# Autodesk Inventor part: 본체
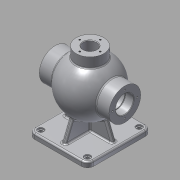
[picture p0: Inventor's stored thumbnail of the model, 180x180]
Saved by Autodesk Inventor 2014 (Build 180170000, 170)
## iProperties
Created: 2015-10
Part Number: 본체
Material: 알루미늄 6061
Document SubType Name: Modeling
Designer: youjin05
Density: 2.71 g/cm^3
Appearance: 알루미늄 - 평지
Mass: 1509.57 g
Surface Area: 1153.7 cm^2
Volume: 557.037 cm^3
Author: youjin05
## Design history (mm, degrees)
sketch "스케치1"
  geometry: L1 (-57.5, -62.5)-(57.5, -62.5); L2 (57.5, -62.5)-(57.5, 62.5); L3 (57.5, 62.5)-(-57.5, 62.5); L4 (-57.5, 62.5)-(-57.5, -62.5); L5 (-57.5, -62.5)-(57.5, 62.5); L6 (57.5, -62.5)-(-57.5, 62.5); 1 further point
  constraints: 12 end point, 2 midpoint, 2 parallel, 1 horizontal, 1 perpendicular
  dimensions: "d0" = 115 distance of L3.end L2.end; "d1" = 125 distance of L2.end L1.end
extrude "돌출1" new body sketch "스케치1" distance "d2" = 10; taper "d3" = 0 deg
sketch "스케치2"
  geometry: L1 (-57.5, 0)-(57.5, 0) reference; L2 (0, 32)-(0, 138); A1 r 53 centre (0, 85) between (0, 32) and (0, 138); 5 further points
  constraints: 3 midpoint, 3 point on circle, 3 vertical alignment, 2 end point, 1 centre point, 1 horizontal alignment, 1 perpendicular
  dimensions: "d6" = 53 radius of A1; "d7" = 85 distance of point (0, 0) A1.centre
revolve "회전1" sketch "스케치2" stored, may be unused: angle "d8" = 90 deg
node "작업 평면1"
sketch "스케치3"
  geometry: C1 r 53 at (0, 85) reference; C2 r 31 at (0, 85); 1 further point
  constraints: 1 centre point, 1 coincident
  dimensions: "d10" = 62 diameter of C2
extrude "돌출2" join sketch "스케치3" distance "d11" = 136; taper "d12" = 0 deg
node "작업 평면2"
sketch "스케치4"
  geometry: C1 r 27 at (0, 0); 1 further point
  constraints: 1 centre point, 1 coincident
  dimensions: "d14" = 54 diameter of C1
extrude "돌출3" join sketch "스케치4" stored distance "d15" = 136; taper "d16" = 0 deg
sketch "스케치5"
  geometry: L1 (-33.719, 44.109)-(-47.5, 10); L2 (-57.5, 0)-(57.5, 0) reference; L3 (57.5, 0)-(57.5, 10) reference; L4 (-57.5, 10)-(57.5, 10) reference; L5 (-57.5, 0)-(-57.5, 10) reference; L6 (-57.5, 10)-(57.5, 10) reference; L7 (-57.5, 0)-(-57.5, 10) reference; L8 (33.719, 44.109)-(47.5, 10); A1 r 53 centre (0, 85) between (-42.988, 54) and (-42.988, 116) reference; 1 further point
  constraints: 4 end point, 2 point on circle, 2 point on line
  dimensions: "d19" = 10 distance of L4.start L1.end; "d20" = 22 deg angle of L5 L1; "d93" = 22 deg angle of L8 L3; "d94" = 10 distance of L3.end L8.end
  node "투영된 루프1"
sketch "스케치6"
  geometry: L1 (-4, -4)-(4, -4); L2 (4, -4)-(4, 4); L3 (4, 4)-(-4, 4); L4 (-4, 4)-(-4, -4); L5 (-4, -4)-(4, 4); L6 (4, -4)-(-4, 4); 1 further point
  constraints: 12 end point, 2 midpoint, 2 parallel, 1 horizontal, 1 perpendicular
  dimensions: "d21" = 8 distance of L3.end L2.end; "d22" = 8 distance of L2.end L1.end
extrude "돌출4" join sketch "스케치6" stored distance "d23" = 136; taper "d24" = 0 deg
sketch "스케치7"
  geometry: L1 (62.5, 10)-(-62.5, 10) reference; L2 (-37.379, 47.426)-(-52.5, 10); L3 (37.379, 47.426)-(52.5, 10); L4 (62.5, 0)-(62.5, 10) reference; L5 (-62.5, 0)-(-62.5, 10) reference; A1 r 53 centre (0, 85) between (-27, 130.607) and (27, 130.607) reference; 1 further point
  constraints: 4 end point, 2 point on circle, 2 point on line
  dimensions: "d27" = 10 distance of L1.start L3.end; "d28" = 22 deg angle of L4 L3; "d29" = 10 distance of L1.end L2.end; "d30" = 22 deg angle of L5 L2
sketch "스케치8"
  geometry: C1 r 27 at (0, 0) reference; 5 further points
  dimensions: "d33" = 91 distance of point (-45.5, 50.5) point (45.5, 50.5); "d34" = 101 distance of point (45.5, 50.5) point (45.5, -50.5); "d35" = 45.5 horizontal distance of point (0, 0) point (45.5, 50.5); "d36" = 50.5 vertical distance of point (0, 0) point (45.5, 50.5); "d37" = 50.5 vertical distance of C1.centre point (-45.5, 50.5); "d38" = 50.5 vertical distance of point (-45.5, -50.5) point (0, 0); "d39" = 91 distance of point (45.5, -50.5) point (-45.5, -50.5); "d40" = 45.5 horizontal distance of point (0, 0) point (-45.5, -50.5)
hole "구멍1" sketch "스케치8" at (-45.5, 50.5), (45.5, 50.5), (45.5, -50.5), (-45.5, -50.5) diameter "d41" = 8; stored, may be unused: countersink angle "d45" = 90 deg, drill point angle "d47" = 118 deg; dims "d42" = 6, "d43" = 12, "d44" = 3, "d46" = 8
sketch "스케치9"
  geometry: L1 (0, 128)-(0, 42); A1 r 53 centre (0, 85) between (-42.988, 54) and (-42.988, 116) reference; A2 r 43 centre (0, 85) between (0, 42) and (0, 128); 2 further points
  constraints: 2 coincident, 2 end point, 2 point on circle, 1 centre point, 1 midpoint, 1 vertical
  dimensions: "d48" = 43 radius of A2
revolve "회전2" sketch "스케치9" stored, may be unused: angle "d49" = 90 deg
sketch "스케치10"
  geometry: C1 r 31 at (0, 0) reference; C2 r 17.5 at (0, 0); 1 further point
  constraints: 1 centre point, 1 coincident
  dimensions: "d50" = 35 diameter of C2
extrude "돌출7" cut sketch "스케치10" stored distance "d51" = 8; taper "d52" = 0 deg
sketch "스케치11"
  geometry: C1 r 27 at (0, 0) reference; C2 r 13 at (0, 0)
  constraints: 1 centre point, 1 coincident
  dimensions: "d53" = 26 diameter of C2
extrude "돌출8" cut sketch "스케치11" stored distance "d54" = 8; taper "d55" = 0 deg
sketch "스케치12"
  geometry: L1 (-50.25, 103.5)-(-50.25, 85); L2 (-68, 67.5)-(-68, 102.5) reference; L3 (-50.25, 103.5)-(-52, 103.5); L4 (-52, 103.5)-(-52, 85); L5 (-52, 85)-(-50.25, 85); 2 further points
  constraints: 8 end point, 3 perpendicular, 1 horizontal alignment, 1 midpoint, 1 vertical
  dimensions: "d57" = 18.5 distance of L1.start L1.end; "d58" = 1.75 distance of L1.start L3.end; "d122" = 16 distance between parallel lines of L2 L4
revolve "회전3" sketch "스케치12" stored, may be unused: angle "d59" = 90 deg
sketch "스케치13"
  geometry: C1 r 17.5 at (0, 0) reference; C2 r 31 at (0, 0) reference; A1 r 24 centre (0, 0) between (-24, 0) and (0, 24); 3 further points
  constraints: 4 point on circle, 2 horizontal alignment, 2 vertical alignment, 1 centre point, 1 coincident
  dimensions: "d60" = 48 diameter of A1
hole "구멍2" sketch "스케치13" at (-24, 0), (0, 24), (24, 0), (0, -24) diameter "d61" = 3.242; stored, may be unused: countersink angle "d65" = 90 deg, drill point angle "d67" = 118 deg; dims "d62" = 16, "d63" = 12, "d64" = 3, "d66" = 19
sketch "스케치14"
  geometry: C1 r 13 at (0, 0) reference; C2 r 27 at (0, 0) reference; A1 r 20 centre (0, 0) between (0, 20) and (20, 0); 2 further points
  constraints: 4 point on circle, 2 horizontal alignment, 2 vertical alignment, 1 centre point, 1 coincident
  dimensions: "d68" = 40 diameter of A1
hole "구멍3" sketch "스케치14" at (0, 20), (20, 0), (0, -20), (-20, 0) diameter "d69" = 3.242; stored, may be unused: countersink angle "d73" = 90 deg, drill point angle "d75" = 118 deg; dims "d70" = 9, "d71" = 12, "d72" = 3, "d74" = 11
sketch "스케치15"
  geometry: C1 r 17.5 at (0, 0) reference; C2 r 31 at (0, 0) reference; A1 r 22.5 centre (0, 0) between (22.5, 0) and (0, -22.5); 3 further points
  constraints: 4 point on circle, 2 horizontal alignment, 2 vertical alignment, 1 centre point, 1 coincident
  dimensions: "d76" = 45 diameter of A1
hole "구멍4" sketch "스케치15" at (22.5, 0), (0, 22.5), (-22.5, 0), (0, -22.5) diameter "d77" = 3.242; stored, may be unused: countersink angle "d81" = 90 deg, drill point angle "d83" = 118 deg; dims "d78" = 12, "d79" = 12, "d80" = 3, "d82" = 15
chamfer "모따기1" distance "d84" = 1; stored, may be unused: second distance "d85" = 2, angle "d86" = 45 deg
fillet "모깎기1" dims "d87" = 3
fillet "모깎기2" dims "d88" = 12
fillet "모깎기3" dims "d89" = 3
feature "리브1" dims "d95" = 1, "d96" = 8, "d97" = 0, "d98" = 0, "d99" = 1, "d100" = 1
feature "리브2" dims "d101" = 1, "d102" = 8, "d103" = 0, "d104" = 0, "d105" = 1, "d106" = 1
node "작업 평면3"
node "작업 평면4"
sketch "스케치17" dims "d10" = 62
  geometry: L1 (-27, 0)-(27, 0) reference; 2 further points
  constraints: 1 vertical alignment, 1 other
  dimensions: "d115" = 10 distance from line of L1 point (0, -10)
feature "엠보싱2" sketch "스케치17" dims "d116" = 0.5, "d117" = 0
sketch "스케치18"
  geometry: L1 (-45.5, 10)-(45.5, 10) reference; L2 (39.5, 10)-(51.5, 10) reference; L3 (33.719, 44.109)-(47.5, 10); L4 (57.5, 7)-(57.5, 0) reference; A1 r 53 centre (0, 85) between (-42.113, 52.821) and (-42.113, 117.179) reference; A2 r 54.948 centre (54.5, 7) between (0, 0) and (0, 0) reference; 1 further point
  constraints: 2 end point, 1 point on circle, 1 point on line
  dimensions: "d118" = 10 distance from line of L4 L3.end; "d119" = 22 deg angle of L4 L3
fillet "모깎기9" dims "d120" = 3
fillet "모깎기10" dims "d121" = 3
node "솔리드1"
mirror "대칭1"
mirror "대칭2"
other parameters: "d9" = -68
